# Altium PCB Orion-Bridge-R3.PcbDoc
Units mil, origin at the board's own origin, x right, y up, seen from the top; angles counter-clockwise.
Board outline 2125.98 x 1417.32 mil, 2 copper layers (Top Layer, Bottom Layer), stack 62.992 mil thick; 28 components, 21 nets, 91 pads, 27 vias.
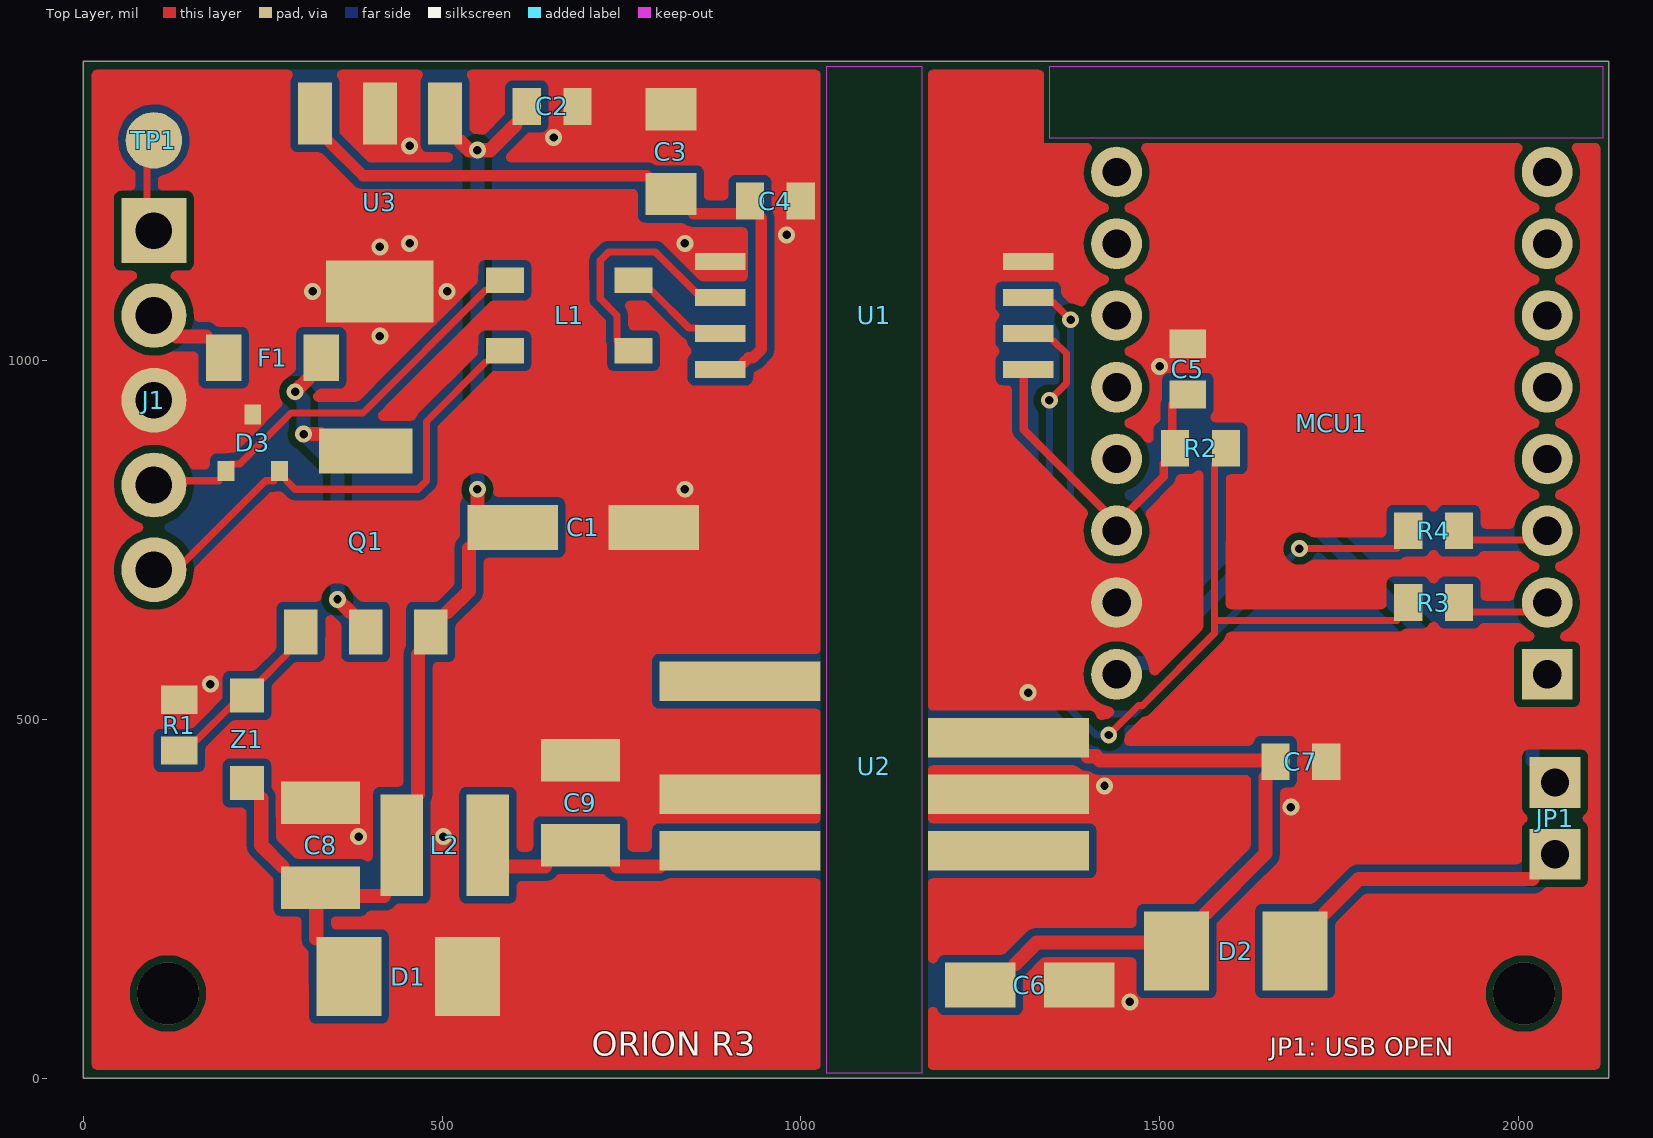
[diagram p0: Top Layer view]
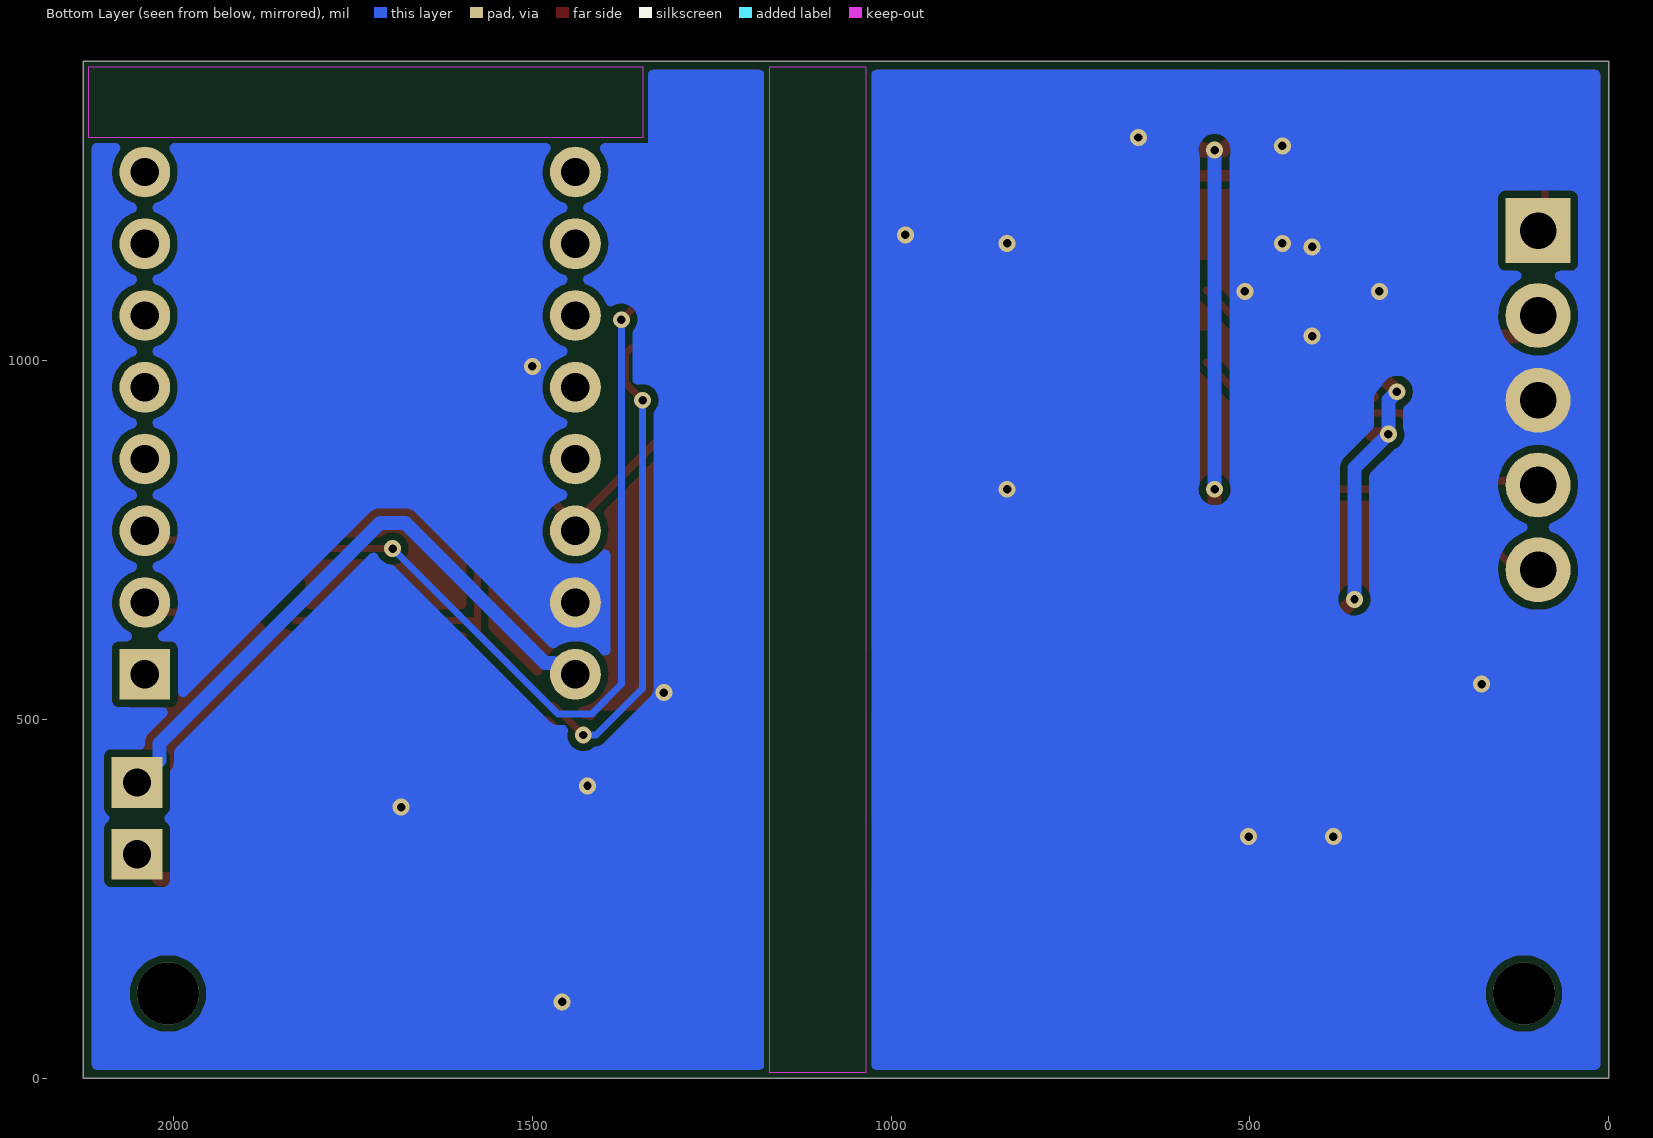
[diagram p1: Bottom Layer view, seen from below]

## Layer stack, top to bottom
Top Layer: signal copper 1.378
Dielectric: dielectric 60.2362, FR-4, Dk 4.3
Bottom Layer: signal copper 1.378

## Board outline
0,0 2125.98,0 2125.98,1417.32 0,1417.32

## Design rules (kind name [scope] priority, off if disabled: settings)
Clearance [All] p0: scope1count=1 scope1_0_kind=Board scope1_0_value=Board scope2count=1 scope2_0_kind=Board scope2_0_value=Board commentlength=0 gap=7.87
Clearance [All] p1: gap=7.87
ComponentClearance [All] p0: scope1count=1 scope1_0_kind=Board scope1_0_value=Board scope2count=1 scope2_0_kind=Board scope2_0_value=Board commentlength=0 gap=9.84 collisioncheckmode=3 verticalgap=9.84 showdistances=FALSE
ComponentClearance [All] p1: gap=9.84 collisioncheckmode=3 verticalgap=9.84 showdistances=FALSE
MinimumSolderMaskSliver [All] p0: scope1count=1 scope1_0_kind=Board scope1_0_value=Board scope2count=1 scope2_0_kind=Board scope2_0_value=Board commentlength=0 minsoldermaskwidth=3.94
MinimumSolderMaskSliver [All] p1: minsoldermaskwidth=3.94
RoutingVias [All] p0: scope1count=1 scope1_0_kind=Board scope1_0_value=Board scope2count=1 scope2_0_kind=Board scope2_0_value=Board commentlength=0 holewidth=11.81 width=23.62 viastyle="Through Hole" minholewidth=11.81 maxholewidth=11.81 minwidth=23.62 maxwidth=23.62
RoutingVias [All] p1: holewidth=11.81 width=23.62 viastyle="Through Hole" minholewidth=11.81 maxholewidth=11.81 minwidth=23.62 maxwidth=23.62
ShortCircuit [All] p0: scope1count=1 scope1_0_kind=Board scope1_0_value=Board scope2count=1 scope2_0_kind=Board scope2_0_value=Board commentlength=0 allowed=FALSE
SolderMaskExpansion TentedVias [IsVia] p0: scope1count=1 scope1_0_kind=Board scope1_0_value=Board scope2count=1 scope2_0_kind=Board scope2_0_value=Board commentlength=0 expansion=-11.81 istentingtop=TRUE istentingbottom=TRUE
SolderMaskExpansion TentedVias [IsVia] p1: expansion=-11.81 istentingtop=TRUE istentingbottom=TRUE
SolderMaskExpansion PadSolderMask [All] p2: expansion=2.95
SolderMaskExpansion PadSolderMask [All] p2: scope1count=1 scope1_0_kind=Board scope1_0_value=Board scope2count=1 scope2_0_kind=Board scope2_0_value=Board commentlength=0 expansion=2.95
UnRoutedNet [All] p0: scope1count=1 scope1_0_kind=Board scope1_0_value=Board scope2count=1 scope2_0_kind=Board scope2_0_value=Board commentlength=0
Width [All] p0: scope1count=1 scope1_0_kind=Board scope1_0_value=Board scope2count=1 scope2_0_kind=Board scope2_0_value=Board commentlength=0 minlimit=9.84 maxlimit=78.74 preferedwidth=11.81
Width [All] p1: minlimit=9.84 maxlimit=78.74 preferedwidth=11.81
2 further rules are at their usual default settings.

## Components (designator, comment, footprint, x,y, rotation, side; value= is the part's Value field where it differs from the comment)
C1 "47uF 50V" PANASONIC_FT_D6P3 696.85,767.72 r0 top
C2 "1uF 50V X7R" C0805 653.54,1354.33 r0 top
C3 "10uF 16V X7R" C1206 818.9,1291.34 r90 top
C4 "100nF 16V X7R" C0805 964.57,1222.44 r0 top
C5 "100nF 16V X7R" C0805 1539.37,988.19 r90 top
C6 "47uF 16V" PANASONIC_FT_D4 1318.9,129.92 r0 top
C7 "100nF 16V X7R" C0805 1696.85,440.94 r0 top
C8 "10uF 50V X7R" C1210 330.71,324.8 r90 top
C9 "10uF 50V X7R" C1210 692.91,383.86 r90 top
D1 "SMBJ20A" SMB 452.76,141.73 r0 top
D2 "SS36" SMB 1606.3,177.17 r180 top
D3 "PESD2CAN24T-Q" SOT23_NEXPERIA_REFLOW 236.22,885.83 r0 top
F1 "T0.8A 63VDC" BOURNS_SF1206S 263.78,1003.94 r0 top
J1 "NMEA Micro-C pigtail" PIGTAIL_5_P3_D1P3 98.43,944.88 r0 top
JP1 "RUN closed / USB open" HDR1X2_2.54 2051.18,362.2 r90 top
L1 "ACT45B-510-2P-TL003" ACT45B 677.17,1062.99 r0 top
L2 "15uH 1A" BOURNS_SRN4018 503.94,324.8 r0 top
MCU1 "ESP32-C3 SuperMini" NOLOGO_C3_SUPERMINI_THT_2X8 1740.16,944.88 r180 top
Q1 "DMP6023LE" SOT223_DIODES_DMP6023LE 393.7,748.03 r0 top
R1 "100k" R0805 133.86,492.13 r90 top
R2 "10k" R0805 1557.09,877.95 r0 top
R3 "33R" R0805 1881.89,662.97 r180 top
R4 "33R" R0805 1881.89,762.97 r0 top
TP1 "Shield / chassis pad" TESTPOINT_2MM 98.43,1307.09 r0 top
U1 "ISO1042DWV" SOIC8_DWV 1102.36,1062.99 r180 top
U2 "R3M-2405S/SMD" R3M_SMD 1102.36,435.04 r0 top
U3 "TPS7B6950QDCYRQ1" SOT223_LDO 413.39,1220.47 r180 top
Z1 "BZT52C12" SOD123 228.35,472.44 r90 top

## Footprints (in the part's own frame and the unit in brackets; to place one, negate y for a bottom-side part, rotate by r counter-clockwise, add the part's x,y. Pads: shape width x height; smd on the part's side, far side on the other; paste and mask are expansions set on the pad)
ACT45B [mm] "TDK ACT45B recommended lands; windings 1-4 and 2-3"
  rect 1.35x0.9 smd: 1(-2.275,1.25) 2(-2.275,-1.25) 3(2.275,-1.25) 4(2.275,1.25)
  body extent -2.58,-1.6 2.57,1.6, height 2.8
BOURNS_SF1206S [mm] "Bourns SF-1206S recommended land pattern: total X span 4.7, inner gap 2.2, pad Y 1.65; maximum body envelope. No polarity."
  rect 1.25x1.65 smd: 1(-1.725,0) 2(1.725,0)
  body extent -1.6,-0.83 1.6,0.83, height 0.72
BOURNS_SRN4018 [mm] "Bourns SRN4018 recommended land pattern: 4.55 total X, two 1.5 x 3.6 pads. Maximum body envelope 4.2 x 4.2. No polarity."
  rect 1.5x3.6 smd: 1(-1.525,0) 2(1.525,0)
  body extent -2.1,-2.1 2.1,2.1, height 1.8
C0805 [mm] "0805 generic capacitor lands; MPN review"
  rect 1x1.3 smd: 1(-0.9,0) 2(0.9,0)
  body extent -1,-0.64 1,0.64, height 1.22
C1206 [mm] "1206 generic capacitor lands; effective capacitance review"
  rect 1.5x1.8 smd: 1(-1.5,0) 2(1.5,0)
  body extent -1.6,-0.81 1.6,0.81, height 1.63
C1210 [mm] "1210 generic capacitor lands; effective capacitance review"
  rect 1.5x2.8 smd: 1(-1.5,0) 2(1.5,0)
  body extent -1.6,-1.26 1.6,1.26, height 2.52
HDR1X2_2.54 [mm] "TBD 2.54 mm service jumper; open BEFORE connecting USB"
  rect 1.8x1.8 hole 1: 1(-1.27,0) 2(1.27,0)
  body extent -2.55,-1.27 2.55,1.27, height 7.2
NOLOGO_C3_SUPERMINI_THT_2X8 [mm] "Nologo 16-pin carrier interface; 15.24 mm rows / 2.54 mm pitch. Local assembly-model height 7.2 mm assumes 3.1 mm carrier-to-module underside, 1.0 mm module PCB and 3.1 mm USB body. This is not a verified manufacturer maximum; actual header seating and module revision must be checked."
  round 1.8 hole 1: 0(7.62,-8.079) 1(7.62,-5.539) 2(7.62,-2.999) 3(7.62,-0.459) 3V3(7.62,4.621) 4(7.62,2.081) 5V(7.62,9.701) 6(-7.62,7.161) 7(-7.62,4.621) 8(-7.62,2.081) 9(-7.62,-0.459) 10(-7.62,-2.999) 20(-7.62,-5.539) 21(-7.62,-8.079) GND(7.62,7.161)
  rect 1.8x1.8 hole 1: 5(-7.62,9.701)
  body extent -9,-11.25 9,11.75, height 7.2
PANASONIC_FT_D4 [mm] "Panasonic FT standard size B land pattern: a=1.0 gap, b=2.5 pad length, c=1.6 pad width. Body is maximum plastic-base envelope; can nominal diameter 4.0. Pin 1 positive, pin 2 negative."
  rect 2.5x1.6 smd: 1(-1.75,0) 2(1.75,0)
  body extent -2.69,-2.15 2.69,2.15, height 6.11
PANASONIC_FT_D6P3 [mm] "Panasonic FT standard size D land pattern: a=1.8 gap, b=3.2 pad length, c=1.6 pad width. Body is maximum plastic-base envelope; can nominal diameter 6.3. Pin 1 positive, pin 2 negative."
  rect 3.2x1.6 smd: 1(-2.5,0) 2(2.5,0)
  body extent -3.7,-3.3 3.7,3.3, height 6.11
PIGTAIL_5_P3_D1P3 [mm] "Designed carrier wire-solder interface, 3.0 pitch, 1.3 finished-hole target, 0.5 radial annulus. Pin numbering is logical NMEA: 1 shield, 2 NET-S, 3 NET-C, 4 CAN-H, 5 CAN-L. Cable and strain relief still require a physical selection."
  rect 2.3x2.3 hole 1.3: 1(0,6)
  round 2.3 hole 1.3: 2(0,3) 3(0,0) 4(0,-3) 5(0,-6)
  body extent -0.8,-6.8 0.8,6.8, height 6
R3M_SMD [mm] "RECOM recommended R3M SMD land pattern; 3.8 mm inner pad gap"
  rect 5.7x1.4 smd: 1(-4.75,-3) 2(-4.75,-1) 4(-4.75,3) 5(4.75,-3) 6(4.75,-1) 7(4.75,1)
  body extent -7.46,-4.55 7.46,4.55, height 10.23
R0805 [mm] "0805 generic resistor lands; MPN review"
  rect 1x1.3 smd: 1(-0.9,0) 2(0.9,0)
  body extent -1,-0.64 1,0.64, height 0.63
SMB [mm] "DO-214AA SMB generic lands; 1=cathode 2=anode; verify vendor"
  rect 2.3x2.8 smd: 1(-2.1,0) 2(2.1,0)
  body extent -2.73,-1.8 2.73,1.8, height 2.51
SOD123 [mm] "SOD-123 generic lands; 1=cathode 2=anode; verify vendor"
  rect 1.2x1.2 smd: 1(-1.55,0) 2(1.55,0)
  body extent -1.85,-0.8 1.85,0.8, height 1.21
SOIC8_DWV [mm] "TI DWV0008A manufacturer land pattern; pin 1 upper left"
  rect 1.8x0.6 smd: 1(-5.45,1.905) 2(-5.45,0.635) 3(-5.45,-0.635) 4(-5.45,-1.905) 5(5.45,-1.905) 6(5.45,-0.635) 7(5.45,0.635) 8(5.45,1.905)
  body extent -5.75,-2.93 5.75,2.93, height 2.82
SOT23_NEXPERIA_REFLOW [mm] "Nexperia SOT23 reflow footprint Fig10: 0.6 x 0.7 copper lands, 1.9 pin pitch and 2.0 row centres. Drawing is rotated 180 degrees to match existing top-view pin1 lower left, pin2 lower right, pin3 upper centre. Paste suggested0.5 x0.6, mask opening1.0 x1.0; set fabrication-specific expansions accordingly."
  rect 0.6x0.7 smd: 1(-0.95,-1) 2(0.95,-1) 3(0,1)
  body extent -1.5,-1.3 1.5,1.3, height 1.11
SOT223_DIODES_DMP6023LE [mm] "Diodes DMP6023LE datasheet suggested SOT223 pad layout: C=2.30, C1=6.40, X=1.20, X1=3.30, Y=Y1=1.60. Pin 1 gate, 2 drain, 3 source, 4 drain tab."
  rect 1.2x1.6 smd: 1(-2.3,-3.2) 2(0,-3.2) 3(2.3,-3.2)
  rect 3.3x1.6 smd: 4(0,3.2)
  body extent -3.27,-3.52 3.27,3.52, height 1.67
SOT223_LDO [mm] "TI TPS7B69-Q1 DCY package drawing4202506/B p20: maximum body6.7x3.7, maximum height1.8, lead pitch2.3. Existing R2 engineering lands retained: 1.2x2.2 signal pads,3.8x2.2 tab,6.3 row centres. TI datasheet provides no DCY recommended land pattern; qualify solder process. Pin4 is GND_BUS tab."
  rect 1.2x2.2 smd: 1(-2.3,-3.15) 2(0,-3.15) 3(2.3,-3.15)
  rect 3.8x2.2 smd: 4(0,3.15)
  body extent -3.35,-3.48 3.35,3.47, height 1.82
TESTPOINT_2MM [mm] "2 mm exposed top-copper test pad; no paste"
  round 2 smd: 1(0,0)
  body extent -1,-1 1,1, height 0.04

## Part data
C1: library part CAP_PANASONIC_EEEFT1H470AP, "47 uF 50 V FT-series SMD aluminum electrolytic, size D, standard product"
C2: library part C_0805_1UF_50V_X7R, "1uF 50V X7R - generic specification; manufacturer/MPN not selected"
C3: library part C_1206_10UF_16V_X7R, "10uF 16V X7R - generic specification; manufacturer/MPN not selected"
C4 C5 C7: library part C_0805_100NF_16V_X7R, "100nF 16V X7R - generic specification; manufacturer/MPN not selected"
C6: library part CAP_PANASONIC_EEEFT1C470AR, "47 uF 16 V FT-series SMD aluminum electrolytic, size B, standard product"
C8 C9: library part C_1210_10UF_50V_X7R, "10uF 50V X7R - generic specification; manufacturer/MPN not selected"
D1: library part SMBJ20A_SMB_GENERIC, "SMBJ20A - generic specification; manufacturer/MPN not selected"
D2: library part SS36_SMB_GENERIC, "SS36 - generic specification; manufacturer/MPN not selected"
D3: library part PESD2CAN24T-QR
F1: library part FUSE_BOURNS_SF1206S080, "0.8 A slow-blow SMD ceramic fuse, 63 VDC, 50 A interrupt rating"
J1: library part NMEA_PIGTAIL_5_P3_D1P3, "Five direct wire-solder pads for a separately selected Micro-C cable; this is a PCB interface, not an invented connector MPN or face view"
JP1: library part JUMPER_1X2_P2_54, "RUN closed / USB open - generic specification; manufacturer/MPN not selected"
L1: library part ACT45B5102PTL003
L2: library part IND_BOURNS_SRN4018_150M, "15 uH semi-shielded power inductor, 1.0 A RMS and 1.1 A saturation rating"
MCU1: library part ESP32_C3_SUPERMINI_NOLOGO, "Nologo ESP32-C3 SuperMini module, two 1x8 carrier headers, GPIO6 TX / GPIO7 RX"
R1: library part R_0805_100K, "100k - generic specification; manufacturer/MPN not selected"
R2: library part R_0805_10K, "10k - generic specification; manufacturer/MPN not selected"
R3 R4: library part R_0805_33R, "33R - generic specification; manufacturer/MPN not selected"
TP1: library part TESTPOINT_2MM, "Shield / chassis pad - generic specification; manufacturer/MPN not selected"
U2: library part R3M-2405S_SMD
Z1: library part BZT52C12_SOD123_GENERIC, "BZT52C12 - generic specification; manufacturer/MPN not selected"

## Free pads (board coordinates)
  round 86.61 hole 86.61 unplated mask+3.94: ""(118.11,118.11) ""(2007.87,118.11)

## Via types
v1: diameter 23.62, hole 11.81, Top Layer to Bottom Layer, tented both sides, 27 vias

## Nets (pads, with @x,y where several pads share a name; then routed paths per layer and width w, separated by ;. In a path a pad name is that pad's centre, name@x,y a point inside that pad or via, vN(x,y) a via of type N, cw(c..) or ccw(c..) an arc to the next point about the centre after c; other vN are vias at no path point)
3V3_LOGIC: C5.1 MCU1.3V3 R2.1 U1.1 | length 355.4
  Top Layer w11.81: U1.1@1311.02,980.32 1311.02,903.54 MCU1.3V3@1423.23,791.34 ; MCU1.3V3@1458.66,791.34 1505.91,838.58 R2.1@1505.91,856.3 ; R2.1@1517.72,903.54 C5.1@1517.72,938.98
5V_AFTER_DIODE: D2.1 JP1.1 | length 308.9
  Top Layer w19.68: D2.1@1730.32,230.31 1777.56,277.56 JP1.1@2019.68,277.56
5V_BUS: C3.1 C4.1 U1.8 U3.3 | length 741.5
  Top Layer w15.75: U3.3@342.52,1305.12 389.76,1257.87 C3.1@785.43,1257.87 ; C3.1@850.39,1204.72 C4.1@915.35,1204.72 ; U1.8@921.26,998.03 927.17,1003.94 933.07,1003.94 944.88,1015.75 C4.1@944.88,1198.82
5V_ISO: C6.1 C7.1 D2.2 U2.7 | length 669
  Top Layer w19.68: 1299.21,159.45 1328.74,188.98 D2.2@1482.28,188.98 ; U2.7@1399.61,448.82 1411.42,448.82 1417.32,442.91 C7.1@1647.64,442.91 ; D2.2@1564.96,230.31 1647.64,312.99 C7.1@1647.64,419.29
5V_MODULE: JP1.2 MCU1.5V | length 780.8
  Bottom Layer w19.68: MCU1.5V@1470.47,578.74 1482.28,578.74 1677.17,773.62 1712.6,773.62 2019.68,466.54 JP1.2@2019.68,442.91
BUS_PROT: C1.1 C2.1 C8.1 D1.1 L2.1 Q1.3 U3.1 Z1.1 | length 1071.6
  Top Layer w19.68: Z1.1@248.03,389.76 248.03,324.8 277.56,295.28 ; 324.8,194.88 C8.1@324.8,236.22 ; C8.1@383.86,253.94 L2.1@419.29,253.94 ; 466.54,395.67 Q1.3@466.54,590.55 ; Q1.3@507.87,649.61 537.4,679.13 C1.1@537.4,738.19 ; U3.1@525.59,1305.12 537.4,1293.31 v1(549.21,1293.31) 566.93,1293.31 C2.1@602.36,1328.74 ; C1.1@549.21,797.24 v1(549.21,820.87)
  Bottom Layer w19.68: v1(549.21,820.87) v1(549.21,1293.31)
CANH: L1.4 U1.7 | length 87
  Top Layer w9.84: L1.4@791.34,1098.43 844.49,1045.28 U1.7@856.3,1045.28
CANH_EXT: D3.1 J1.4 L1.1 | length 501.9
  Top Layer w9.84: J1.4@141.73,832.68 D3.1@188.98,832.68 ; D3.1@206.69,856.3 218.5,856.3 289.37,927.17 389.76,927.17 L1.1@561.02,1098.43
CANL: L1.3 U1.6 | length 287.2
  Top Layer w9.84: L1.3@744.09,1027.56 744.09,1062.99 720.47,1086.61 720.47,1139.76 732.28,1151.57 797.24,1151.57 U1.6@856.3,1092.52
CANL_EXT: D3.2 J1.5 L1.2 | length 574.8
  Top Layer w9.84: J1.5@141.73,720.47 253.94,832.68 D3.2@265.75,832.68 ; D3.2@283.46,832.68 295.28,820.87 466.54,820.87 478.35,832.68 478.35,915.35 L1.2@561.02,998.03
DCDC_IN: C9.1 L2.2 U2.1 | length 112.2
  Top Layer w19.68: L2.2@590.55,295.28 C9.1@643.7,295.28 ; C9.1@744.09,295.28 U2.1@803.15,295.28
FUSED_IN: F1.2 Q1.2 Q1.4 | length 387.6
  Top Layer w19.68: v1(295.28,956.69) F1.2@312.99,974.41 ; v1(307.09,897.64) Q1.4@330.71,897.64 ; v1(354.33,667.32) Q1.2@372.05,649.61
  Bottom Layer w19.68: v1(295.28,956.69) 307.09,944.88 v1(307.09,897.64) 354.33,850.39 v1(354.33,667.32)
GATE: Q1.1 R1.1 Z1.2 | length 116.9
  Top Layer w9.84: R1.1@159.45,472.44 Z1.2@206.69,519.68 ; Z1.2@248.03,555.12 Q1.1@283.46,590.55
GND_BUS: C1.2 C2.2 C3.2 C4.2 C8.2 C9.2 D1.2 D3.3 J1.3 R1.2 U1.5 U2.2 U3.2 U3.4 | length 2728
  Top Layer w19.68: v1(319.69,1096.46) U3.4@338.58,1096.46 ; v1(413.39,1034.25) U3.4@413.39,1053.15 ; 413.39,1139.76 v1(413.39,1158.66) ; 488.19,1096.46 v1(507.09,1096.46)
  Top Layer w23.62: J1.3@141.73,933.07 224.41,933.07 ; R1.2@159.45,543.31 171.26,543.31 v1(177.17,549.21) ; 248.03,938.98 248.03,1015.75 295.28,1062.99 U3.4@342.52,1062.99 ; v1(383.86,336.61) 383.86,354.33 ; 437.01,1305.12 448.82,1305.12 v1(454.72,1299.21) ; 454.72,1139.76 v1(454.72,1163.39) ; v1(501.97,336.61) v1@507.87,336.61 ; D1.2@507.87,194.88 507.87,407.48 525.59,425.2 C9.2@643.7,425.2 ; v1(655.51,1311.02) C2.2@673.23,1328.74 ; C2.2@708.66,1328.74 C3.2@785.43,1328.74 ; C9.2@732.28,472.44 C1.2@732.28,738.19 ; 744.09,413.39 U2.2@803.15,413.39 ; C1.2@838.58,797.24 v1(838.58,820.87) ; v1(838.58,1163.39) U1.5@856.3,1145.67 ; C3.2@850.39,1322.83 897.64,1275.59 956.69,1275.59 C4.2@986.22,1246.06 ; v1(980.32,1175.2) C4.2@980.32,1198.82
  Bottom Layer w23.62: v1(177.17,549.21) v1@389.76,336.61 ; v1(383.86,336.61) v1(501.97,336.61) ; v1(454.72,1163.39) v1(454.72,1299.21) 501.97,1299.21 537.4,1334.65 631.89,1334.65 v1(655.51,1311.02) ; v1(838.58,820.87) v1(838.58,1163.39) 850.39,1175.2 v1(980.32,1175.2)
GND_LOGIC: C5.2 C6.2 C7.2 MCU1.GND U1.4 U2.6 | length 1833.4
  Top Layer w23.62: U1.4@1287.4,1127.95 1275.59,1127.95 1251.97,1104.33 1251.97,862.2 MCU1.GND@1423.23,690.94 ; v1(1316.93,537.4) MCU1.GND@1417.32,637.8 ; U2.6@1399.61,407.48 v1(1423.23,407.48) ; C6.2@1435.04,106.3 v1(1458.66,106.3) ; v1(1500,992.13) 1505.91,998.03 1511.81,998.03 C5.2@1517.72,1003.94 ; v1(1683.07,377.95) 1712.6,407.48 1712.6,419.29
  Bottom Layer w23.62: v1(1316.93,537.4) 1316.93,513.78 v1(1423.23,407.48) 1458.66,372.05 v1(1458.66,106.3) ; 1452.76,377.95 v1(1683.07,377.95) ; MCU1.GND@1458.66,690.94 1500,732.28 v1(1500,992.13)
GPIO6: MCU1.6 R3.1 | length 70.9
  Top Layer w9.84: 1937.01,649.61 MCU1.6@2007.87,649.61
GPIO7: MCU1.7 R4.2 | length 70.9
  Top Layer w9.84: 1937.01,750 MCU1.7@2007.87,750
NET_S: F1.1 J1.2 | length 41.3
  Top Layer w19.68: J1.2@129.92,1033.46 F1.1@171.26,1033.46
RXD: R4.1 U1.3 | length 1108.5
  Top Layer w9.84: 1352.36,1080.71 v1(1375.98,1057.09) ; v1(1694.88,738.19) R4.1@1830.71,738.19
  Bottom Layer w9.84: v1(1375.98,1057.09) 1375.98,549.21 1417.32,507.87 1464.57,507.87 v1(1694.88,738.19)
SHIELD: J1.1 TP1.1 | length 47.2
  Top Layer w9.84: J1.1@88.58,1222.44 TP1.1@88.58,1269.68
TXD: R2.2 R3.2 U1.2 | length 1307.5
  Top Layer w9.84: v1(1346.46,944.88) 1370.08,968.5 1370.08,1009.84 1352.36,1027.56 ; v1(1429.13,478.35) 1470.47,519.68 1476.38,519.68 1576.77,620.08 R2.2@1576.77,856.3 ; 1576.77,637.8 R3.2@1830.71,637.8
  Bottom Layer w9.84: v1(1346.46,944.88) 1346.46,543.31 1411.42,478.35 v1(1429.13,478.35)
pads on no net: MCU1.0 MCU1.1 MCU1.2 MCU1.3 MCU1.4 MCU1.5 MCU1.8 MCU1.9 MCU1.10 MCU1.20 MCU1.21 U2.4 U2.5

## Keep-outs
Keep-Out Layer:
  region: 1035.43,7.87 1169.29,7.87 1169.29,1409.45 1035.43,1409.45
  region: 1346.46,1311.02 2118.11,1311.02 2118.11,1409.45 1346.46,1409.45

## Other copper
Top Layer:
  drawing of 67 lines, arcs and shapes, not listed
Bottom Layer:
  region net GND_BUS: 18.9,12.01 17.11,12.24 15.45,12.93 13.43,14.7 12.53,16.26 12.01,18.9 12.01,1398.43 12.24,1400.21 12.93,1401.87 14.7,1403.89 17.11,1405.08 18.9,1405.32 42.32,1405.32 42.32,1135.94 42.32,12.01
  region net GND_BUS: 42.32,12.01 42.32,1135.94 42.38,1135.52 42.38,1064.32 42.33,1063.3 42.38,1062.04 42.38,824.24 42.38,12.01
  region net GND_BUS: 42.38,1405.32 42.38,1226.9 42.33,1226.49 42.32,1135.94 42.32,1405.32
  region net GND_BUS: 42.38,12.01 42.38,824.24 42.9,818.76 43.95,813.36 45.53,808.08 47.62,802.99 50.19,798.12 53.23,793.53 56.71,789.26 60.59,785.36 64.68,781.97 64.68,753.46 60.52,750.02 55.26,744.49 51.95,740.08 49.06,735.3 46.68,730.34 43.93,721.99 42.9,716.67 42.4,711.64 42.63,702.86 43.45,697.5 44.68,692.59 46.51,687.4 48.84,682.41 51.66,677.68 54.92,673.25 58.6,669.15 62.66,665.44 64.68,663.93 64.68,121.5 64.68,114.72 64.68,12.01
  region net GND_BUS: 64.68,1405.32 64.68,1237.2 53.26,1237.2 49.22,1236.45 47.55,1235.63 45.66,1234.18 44.43,1232.78 43.25,1230.72 42.65,1228.96 42.38,1226.9 42.38,1405.32
  region net GND_BUS: 45.66,1128.02 47.94,1126.35 50.13,1125.44 51.96,1125.08 64.68,1125.02 64.68,1107.77 60.98,1104.76 57.01,1100.83 53.23,1096.23 50.19,1091.64 47.62,1086.78 45.53,1081.68 43.93,1076.32 42.63,1068.8 42.38,1064.32 42.38,1135.52 42.76,1132.81 43.9,1130.23
  region net GND_BUS: 42.57,1057.72 43.45,1051.83 44.83,1046.41 47.58,1039.29 50.42,1033.96 53.55,1029.33 57.01,1025.15 60.92,1021.28 64.68,1018.21 64.68,871.55 60.92,868.49 57.01,864.61 53.5,860.37 50.42,855.8 47.81,850.96 45.68,845.88 44.06,840.62 42.97,835.22 42.4,829.75 42.38,824.24 42.38,1062.04
  region net GND_BUS: 64.68,12.01 64.68,114.72 65.04,111.01 66.37,104.36 67.45,100.79 70.04,94.53 71.8,91.24 75.57,85.61 77.93,82.72 82.72,77.93 85.61,75.57 91.24,71.8 94.53,70.04 100.79,67.45 104.36,66.37 111.01,65.04 114.72,64.68 121.5,64.68 125.21,65.04 131.86,66.37 135.43,67.45 141.69,70.04 144.98,71.8 150.61,75.57 153.5,77.93 154.52,78.96 154.52,12.01
  region net GND_BUS: 154.52,1405.32 154.52,1226.29 153.78,1230.31 152.95,1231.98 151.51,1233.86 150.1,1235.09 148.05,1236.28 146.28,1236.88 143.59,1237.2 64.68,1237.2 64.68,1405.32
  region net GND_BUS: 153.5,158.29 150.61,160.65 144.98,164.42 141.69,166.18 135.43,168.77 131.86,169.85 125.21,171.18 121.5,171.54 114.72,171.54 111.01,171.18 104.36,169.85 100.79,168.77 94.53,166.18 91.24,164.42 85.61,160.65 82.72,158.29 77.93,153.5 75.57,150.61 71.8,144.98 70.04,141.69 67.45,135.43 66.37,131.86 65.04,125.21 64.68,121.5 64.68,663.93 67.07,662.14 71.78,659.29 76.75,656.92 81.93,655.04 87.26,653.68 92.7,652.85 98.2,652.56 103.7,652.81 109.15,653.6 114.5,654.91 122.61,658.04 129.85,662.19 133.84,665.15 137.87,668.78 143.35,675.06 148.01,682.41 151.35,690.05 153.51,698.02 154.28,703.39 154.52,708.35 154.52,157.26
  region net GND_BUS: 67.95,1125 69.74,1124.76 72.16,1123.57 73.43,1122.29 74.33,1120.72 74.79,1118.98 74.78,1117.17 74.3,1115.43 72.79,1113.2 65.25,1108.23 64.68,1107.77 64.68,1125.02
  region net GND_BUS: 65.19,1017.8 69.78,1014.76 74.64,1012.18 79.74,1010.1 85.01,1008.52 90.41,1007.47 95.9,1006.95 101.4,1006.97 106.88,1007.53 112.27,1008.63 117.53,1010.25 122.61,1012.37 127.46,1014.99 132.09,1018.12 137.94,1023.17 143.3,1029.33 146.7,1034.42 150.14,1041.24 152.2,1047 153.88,1054.54 154.47,1060.55 154.23,1068.71 153.39,1074.24 151.32,1081.68 149.01,1087.26 145.24,1093.9 141.59,1098.82 136.26,1104.41 131.6,1108.23 124.06,1113.2 122.96,1114.63 122.26,1116.29 122.07,1118.98 122.92,1121.54 124.02,1122.97 125.45,1124.07 127.11,1124.76 128.9,1125 143.81,1125.01 146.28,1125.32 148.05,1125.92 150.46,1127.39 152.14,1129.07 153.6,1131.48 154.2,1133.25 154.52,1135.9 154.52,708.35 153.95,716.67 152.02,725.24 150.34,729.92 148.04,734.83 143.67,741.83 139.78,746.56 133.84,752.17 127,756.94 116.23,762.17 114.39,764.21 113.68,765.9 113.43,767.72 113.68,769.54 114.39,771.23 115.53,772.67 117.01,773.76 125.14,777.44 132.09,781.9 138.31,787.32 141.65,791.01 144.9,795.35 149.01,802.51 151.35,808.16 153.49,816.05 154.47,824.33 154.45,829.75 153.96,834.7 152.2,842.76 149.23,850.56 144.95,858.12 139.78,864.67 135.93,868.49 132.09,871.65 125.07,876.14 117.53,879.52 112.27,881.14 106.88,882.23 101.4,882.79 95.9,882.81 90.41,882.3 85.01,881.24 79.74,879.67 74.64,877.58 69.78,875 65.19,871.96 64.68,871.55 64.68,1018.21
  region net GND_BUS: 83.17,769.54 83.42,767.72 83.17,765.9 81.94,763.45 79.84,761.68 74.24,759.28 69.32,756.62 64.83,753.59 64.68,753.46 64.68,781.97 64.83,781.85 69.39,778.77 74.24,776.15 79.01,774.14 81.32,772.67 82.46,771.23
  region net GND_BUS: 154.52,12.01 154.52,78.96 154.53,78.96
  region net GND_BUS: 154.53,1405.32 154.53,1226.27 154.52,1226.29
  region net GND_BUS: 154.52,157.26 154.52,708.35 154.52,1135.9 154.53,1135.94
  region net GND_BUS: 154.53,12.01 154.53,78.96 158.29,82.72 160.65,85.61 164.42,91.24 166.18,94.53 168.77,100.79 169.85,104.36 171.18,111.01 171.54,114.72 171.54,12.01
  region net GND_BUS: 171.54,1405.32 171.54,121.5 171.18,125.21 169.85,131.86 168.77,135.43 166.18,141.69 164.42,144.98 160.65,150.61 158.29,153.5 154.53,157.26 154.53,1135.94 154.53,1226.27 154.53,1405.32
  region net GND_BUS: 171.54,12.01 171.54,114.72 171.54,121.5 171.54,1405.32 272.65,1405.32 272.65,955.89 272.65,12.01
  region net GND_BUS: 272.65,12.01 272.65,955.89 273.25,951.49 274.68,947.29 276.91,943.46 279.85,940.13 284.5,936.47 285.52,935.07 286.32,932.62 286.42,908.23 286.21,906.55 284.83,901.75 284.45,897.33 285.18,891.92 287.02,887.16 288.77,884.33 291.24,881.47 294.33,878.94 298.63,876.57 299.96,875.53 331.64,843.85 332.74,842.42 333.43,840.76 333.66,838.98 333.66,677.91 331.9,670.34 331.7,667.1 331.91,664.22 333.09,659.49 335.08,655.42 338.11,651.54 341.57,648.63 345.88,646.33 350.22,645.06 355.13,644.7 360.05,645.42 363.2,646.5 366.23,648.07 369.3,650.35 371.69,652.79 373.86,655.88 375.36,658.95 376.36,662.12 376.92,665.9 376.92,12.01
  region net GND_BUS: 376.92,1405.32 376.92,665.9 376.69,670.87 375,677.91 375,850.35 374.27,855.8 372.34,860.52 369.34,864.59 329.77,904.18 328.68,905.61 327.99,907.27 327.76,909.05 327.75,944.92 327.46,948.31 326.72,951.31 325.51,954.23 323.92,956.87 316.82,964.45 312.97,970.81 310.31,973.61 307.18,975.95 303.19,977.9 298.9,979.04 294.47,979.31 290.07,978.72 285.88,977.28 282.04,975.06 278.71,972.12 276.02,968.59 274.07,964.61 272.93,960.32 272.65,955.89 272.65,1405.32
  region net GND_BUS: 376.92,12.01 376.92,665.9 376.92,1405.32 526.59,1405.32 526.59,1294.19 526.59,12.01
  region net GND_BUS: 526.59,12.01 526.59,1294.19 526.87,1289.68 528.54,1282.72 528.54,831.46 528.34,829.78 527.06,825.5 526.59,821.75 526.79,817.77 527.8,813.53 529.64,809.49 531.91,806.27 535.09,803.17 538.81,800.76 542.94,799.12 547.3,798.31 551.74,798.37 556.08,799.3 560.15,801.05 563.81,803.57 566.9,806.75 569.32,810.47 571.22,815.58 571.85,820.64 571.85,12.01
  region net GND_BUS: 571.85,1405.32 571.85,820.64 571.47,824.98 570.09,829.78 569.88,831.46 569.88,1282.72 571.56,1289.68 571.83,1294.19 571.24,1298.51 570.01,1302.25 567.91,1306.07 565.38,1309.15 562.04,1311.96 558.61,1313.9 554.5,1315.32 550.1,1315.93 545.67,1315.66 541.38,1314.54 537.38,1312.61 533.85,1309.93 530.9,1306.61 528.66,1302.78 527.2,1298.59 526.59,1294.19 526.59,1405.32
  region net GND_BUS: 1023.31,12.53 1020.67,12.01 571.85,12.01 571.85,820.64 571.85,1405.32 1020.67,1405.32 1022.45,1405.08 1024.11,1404.39 1026.14,1402.62 1027.03,1401.06 1027.36,1399.41 1027.36,17.91 1027.03,16.26 1025.54,14.03
  region net GND_LOGIC: 179 vertices and 0 holes, not listed, extent 1177.36,12.01 1954.44,1405.32
  region net GND_LOGIC: 1997,459.99 1998.09,458.56 1998.96,456.02 1999.03,442.42 1999.51,438.45 2000.84,434.44 2003.98,429.36 2004.86,426.79 2005.06,375.14 2005.67,372.84 2006.5,371.17 2007.94,369.29 2011.43,366.03 2012.23,364.42 2012.58,362.66 2012.46,360.86 2011.88,359.16 2010.88,357.66 2007.94,355.12 2006.5,353.24 2005.36,350.65 2005,348.83 2005,275.58 2005.85,272.43 2007.03,270.37 2008.26,268.97 2011.4,266.87 2014.56,266.02 2061.31,266.02 2061.31,121.5 2060.94,125.21 2059.62,131.86 2058.54,135.43 2055.94,141.69 2054.18,144.98 2050.42,150.61 2048.05,153.5 2043.26,158.29 2040.38,160.65 2034.74,164.42 2031.45,166.18 2025.19,168.77 2021.62,169.85 2014.97,171.18 2011.26,171.54 2004.48,171.54 2000.77,171.18 1994.13,169.85 1990.56,168.77 1984.3,166.18 1981.01,164.42 1975.37,160.65 1972.49,158.29 1967.7,153.5 1965.33,150.61 1961.56,144.98 1959.81,141.69 1957.21,135.43 1956.13,131.86 1954.81,125.21 1954.44,121.5 1954.44,502.55
  region net GND_LOGIC: 2047.24,458.46 2045.46,458.7 2043.8,459.39 2042.37,460.48 2040.88,462.72 2040.41,464.45 2040.2,469 2039.63,471.94 2038.53,475.01 2036.61,478.38 2034.27,481.18 2010.5,504.95 2009.01,507.18 2008.49,509.82 2009.01,512.46 2010.5,514.69 2011.93,515.79 2014.48,516.65 2061.31,516.7 2061.31,458.42
  region net GND_LOGIC: 2060.33,611.29 2059.24,612.75 2058.57,614.44 2058.36,616.25 2058.95,618.91 2060.52,621.13 2061.31,621.64 2061.31,610.53
  region net GND_LOGIC: 2055.04,706.83 2053.57,707.84 2051.98,709.96 2051.3,712.52 2051.41,714.3 2051.98,715.98 2053.57,718.1 2055.04,719.1 2061.31,721.87 2061.31,704.07
  region net GND_LOGIC: 2059.73,804.88 2055.04,806.83 2053.57,807.84 2051.98,809.96 2051.41,811.64 2051.3,813.41 2051.98,815.98 2053.57,818.1 2055.04,819.1 2061.31,821.9 2061.31,804.05
  region net GND_LOGIC: 2055.04,906.83 2053.57,907.84 2051.98,909.96 2051.41,911.64 2051.3,913.41 2051.98,915.98 2053.57,918.1 2055.04,919.1 2061.31,921.9 2061.31,904.04
  region net GND_LOGIC: 2055.04,1006.83 2053.57,1007.84 2051.98,1009.96 2051.41,1011.64 2051.3,1013.41 2051.98,1015.98 2053.57,1018.1 2055.04,1019.1 2061.31,1021.9 2061.31,1004.04
  region net GND_LOGIC: 2055.04,1106.83 2053.57,1107.84 2051.98,1109.96 2051.41,1111.64 2051.3,1113.41 2051.98,1115.98 2053.57,1118.1 2055.04,1119.1 2061.31,1121.9 2061.31,1104.04
  region net GND_LOGIC: 2055.04,1206.83 2053.57,1207.84 2051.98,1209.96 2051.41,1211.64 2051.3,1213.41 2051.98,1215.98 2053.57,1218.1 2055.04,1219.1 2061.31,1221.87 2061.31,1204.04
  region net GND_LOGIC: 1954.44,12.01 1954.44,114.72 1954.81,111.01 1956.13,104.36 1957.21,100.79 1959.81,94.53 1961.56,91.24 1965.33,85.61 1967.7,82.72 1972.49,77.93 1975.37,75.57 1981.01,71.8 1984.3,70.04 1990.56,67.45 1994.13,66.37 2000.77,65.04 2004.48,64.68 2011.26,64.68 2014.97,65.04 2021.62,66.37 2025.19,67.45 2031.45,70.04 2034.74,71.8 2040.38,75.57 2043.26,77.93 2048.05,82.72 2050.42,85.61 2054.18,91.24 2055.94,94.53 2058.54,100.79 2059.62,104.36 2060.94,111.01 2061.31,114.72 2061.31,12.01
  region net GND_LOGIC: 192 vertices and 0 holes, not listed, extent 2061.31,12.01 2113.98,1302.95
  region net GND_LOGIC: 385 vertices and 0 holes, not listed, extent 1391.73,531.3 2029.02,1302.95

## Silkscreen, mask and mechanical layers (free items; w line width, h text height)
Top Overlay:
  text "ORION R3" at 708.66,31.5 h33.46
  text "JP1: USB OPEN" at 1653.54,31.5 h25.59
Board outline:
  the board outline again, w3.94
Isolation and RF planning:
  lines w3.94: 1027.56,0 1177.17,0 1177.17,1417.32 1027.56,1417.32 1027.56,0 ; 1338.58,1303.15 2125.98,1303.15 2125.98,1417.32 1338.58,1417.32 1338.58,1303.15
Design notes:
  text "ORION BRIDGE R3 / 54 x 36 mm / 2 layers, FR4 1.6 mm, copper 35 um" at 39.37,-78.74 h35.43
  text "GND_BUS / GND_LOGIC isolated, 3.8 mm minimum; antenna zone copper free." at 39.37,-157.48 h35.43
  text "Open JP1 BEFORE USB. Prototype: thermal and actual module qualification pending." at 39.37,-236.22 h35.43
